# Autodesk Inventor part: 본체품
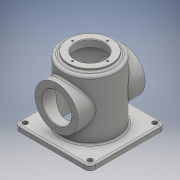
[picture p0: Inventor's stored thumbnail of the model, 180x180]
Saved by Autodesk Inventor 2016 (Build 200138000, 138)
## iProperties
Created: 2019-08
Part Number: 본체품
Material: 일반
Document SubType Name: Modeling
Designer: user
Density: 1 g/cm^3
Appearance: 기본값
Author: user
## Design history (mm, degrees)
node "작업 평면2"
sketch "스케치3"
  geometry: L1 (-70, 70)-(70, 70); L2 (70, 70)-(70, -70); L3 (70, -70)-(-70, -70); L4 (-70, -70)-(-70, 70); L5 (-70, 70)-(70, -70); L6 (70, 70)-(-70, -70); 1 further point
  constraints: 12 end point, 2 midpoint, 2 parallel, 1 horizontal, 1 perpendicular
  dimensions: "d8" = 140 distance of L1.start L1.end; "d9" = 140 distance of L1.end L2.end
extrude "돌출2" new body sketch "스케치3" distance "d10" = 10; taper "d11" = 0 deg
fillet "모깎기2" dims "d12" = 10
sketch "스케치4"
  geometry: C1 r 50 at (0, 0); 1 further point
  constraints: 1 centre point, 1 coincident
  dimensions: "d13" = 100 diameter of C1
extrude "돌출3" join sketch "스케치4" distance "d14" = 110; taper "d15" = 0 deg
sketch "스케치8"
  geometry: C1 r 40 at (0, 0); 1 further point
  constraints: 1 centre point, 1 coincident
  dimensions: "d42" = 80 diameter of C1
extrude "돌출6" join sketch "스케치8" stored distance "d43" = 124; taper "d44" = 0 deg
sketch "스케치5"
  geometry: C1 r 40 at (0, 0); 1 further point
  constraints: 1 centre point, 1 coincident
  dimensions: "d16" = 80 diameter of C1
extrude "돌출4" join sketch "스케치5" distance "d17" = 5; taper "d18" = 0 deg
sketch "스케치6"
  geometry: C1 r 45 at (0, 0); 1 further point
  constraints: 1 centre point, 1 coincident
  dimensions: "d19" = 90 diameter of C1
extrude "돌출5" cut sketch "스케치6" distance "d20" = 112; taper "d21" = 0 deg
hole "구멍1" diameter "d24" = 54; stored, may be unused: countersink angle "d28" = 90 deg, drill point angle "d30" = 118 deg; dims "d22" = 10, "d23" = 10, "d25" = 6, "d26" = 4, "d27" = 2, "d29" = 8
sketch "스케치7" dims "d31" = 65
  geometry: 3 further points
  constraints: 2 horizontal alignment, 1 coincident, 2 other
hole "구멍2" sketch "스케치7" at (32.5, 0) diameter "d32" = 3.242; stored, may be unused: countersink angle "d36" = 90 deg, drill point angle "d38" = 118 deg; dims "d33" = 8, "d34" = 4, "d35" = 2, "d37" = 10
sketch "스케치9"
  geometry: C1 r 27 at (0, 0); 1 further point
  constraints: 1 centre point, 1 coincident
  dimensions: "d45" = 54 diameter of C1
extrude "돌출7" cut sketch "스케치9" stored distance "d46" = 124; taper "d47" = 0 deg
sketch "스케치10" dims "d48" = 65
  geometry: 3 further points
  constraints: 2 horizontal alignment, 1 coincident, 2 other
hole "구멍3" sketch "스케치10" at (32.5, 0) diameter "d49" = 3.242; stored, may be unused: countersink angle "d53" = 90 deg, drill point angle "d55" = 118 deg; dims "d50" = 8, "d51" = 4, "d52" = 2, "d54" = 10
hole "구멍4" diameter "d64" = 9; stored, may be unused: countersink angle "d68" = 90 deg, drill point angle "d70" = 118 deg; dims "d65" = 9, "d66" = 4, "d67" = 2, "d69" = 9, "d71" = 10, "d72" = 10
hole "구멍5" diameter "d75" = 9; stored, may be unused: countersink angle "d79" = 90 deg, drill point angle "d81" = 118 deg; dims "d73" = 10, "d74" = 10, "d76" = 6, "d77" = 4, "d78" = 2, "d80" = 8
fillet "모깎기3" dims "d82" = 5
fillet "모깎기4" dims "d83" = 3
fillet "모깎기5" dims "d84" = 3
fillet "모깎기6" dims "d85" = 3
fillet "모깎기7" dims "d86" = 3
chamfer "모따기1" distance "d87" = 1; stored, may be unused: second distance "d88" = 2, angle "d89" = 45 deg
chamfer "모따기2" distance "d90" = 1; stored, may be unused: second distance "d91" = 2, angle "d92" = 45 deg
chamfer "모따기3" distance "d93" = 1; stored, may be unused: second distance "d94" = 2, angle "d95" = 45 deg
fillet "모깎기8" dims "d96" = 3
node "솔리드2"
pattern_circular "원형 패턴1" dims angle "d40" = 360 deg
pattern_circular "원형 패턴2" dims angle "d57" = 360 deg
mirror "대칭1"
pattern_circular "원형 패턴3" dims angle "d60" = 360 deg
mirror "대칭2"
other parameters: "d7" = -65
